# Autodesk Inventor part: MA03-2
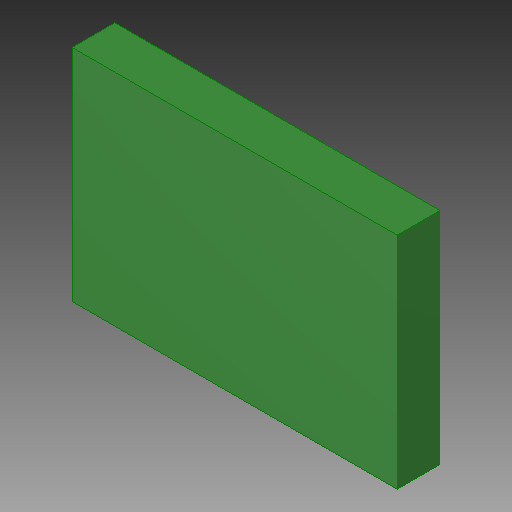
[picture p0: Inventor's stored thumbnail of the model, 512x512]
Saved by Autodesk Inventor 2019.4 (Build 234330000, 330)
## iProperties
Created: 2019-11
Part Number: MA03-2
Material: Generic
Document SubType Name: Modeling
Designer: Willist
Density: 1 g/cm^3
Appearance: MA03-2, MA03-2
Author: Willist
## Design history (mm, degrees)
sketch "MA03-2, MA03-2_139"
  geometry: L1 (-3.81, 2.616)-(3.81, 2.616); L2 (3.81, 2.616)-(3.81, -2.54); L3 (3.81, -2.54)-(-3.81, -2.54); L4 (-3.81, -2.54)-(-3.81, 2.616)
  constraints: 8 end point
extrude "Extrusion1" join sketch "MA03-2, MA03-2_139" distance "d0" = 1; taper "d1" = 0 deg
body "Solid1"
